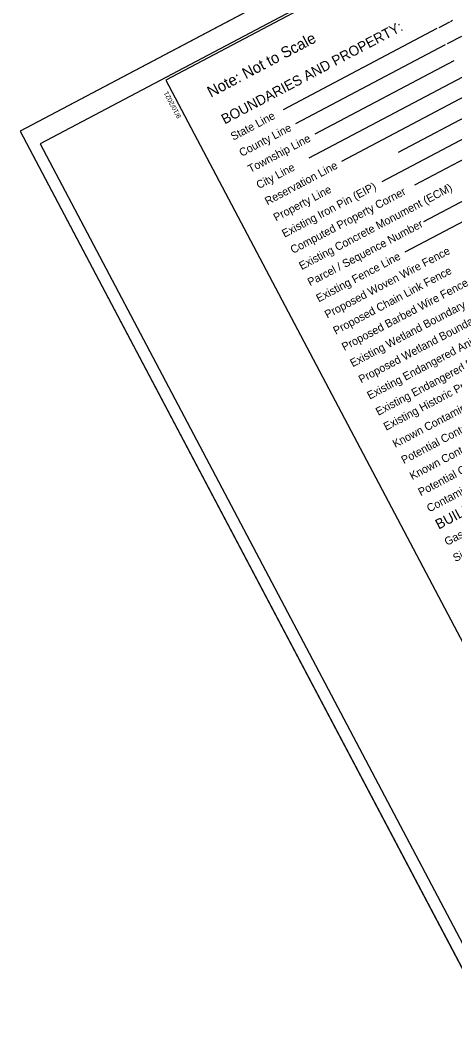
# Model space of a CAD drawing. Extents: x 1487118 to 1489121, y 496367 to 498126.
# Drawn here: x 1487118 to 1487593, y 496367 to 497462 of the extents above; entities that cross this region are included whole.
import ezdxf

# ---------------------------------------------------------------- set-up
doc = ezdxf.new("R2010")
doc.units = 0
for name, color, linetype in [('Sheet Cutting Line CELL', 7, 'Continuous'), ('Sheet Plot Border Inside CELL', 7, 'Continuous'), ('Sheet Plot Border Outside CELL', 7, 'Continuous'), ('Sheet Summary Guardrail CELL', 7, 'Continuous'), ('Sheet Symbology CELL', 7, 'Continuous')]:
    doc.layers.add(name, color=color, linetype=linetype)

msp = doc.modelspace()

# ---------------------------------------------------------------- linework, layer by layer
at = {"layer": 'Sheet Cutting Line CELL'}
for p, q in [((1488607.2, 498126.3), (1487118, 497340)), ((1487118, 497340), (1487631.6, 496367.3))]:
    msp.add_line(p, q, dxfattribs=at)
at = {"layer": 'Sheet Plot Border Inside CELL'}
msp.add_lwpolyline([(1487632.6, 496393.2), (1489106.3, 497171.4), (1488613.7, 498104.4), (1487140, 497326.3)], close=True, dxfattribs=at)
at = {"layer": 'Sheet Plot Border Outside CELL'}
msp.add_lwpolyline([(1487631.6, 496367.3), (1489120.8, 497153.6), (1488607.2, 498126.3), (1487118, 497340)], close=True, dxfattribs=at)
at = {"layer": 'Sheet Symbology CELL'}
for p, q in [((1487576, 497453.5), (1487587.7, 497459.7)), ((1487588.6, 497460.1), (1487590.8, 497461.3)), ((1487573.5, 497452.2), (1487405.5, 497363.5)), ((1487585.3, 497435.8), (1487600.9, 497444)), ((1487582.8, 497434.5), (1487419.2, 497348.1)), ((1487592.1, 497416.8), (1487440.3, 497336.6)), ((1487601.5, 497399.1), (1487433.5, 497310.4)), ((1487610.8, 497381.4), (1487469.3, 497306.7)), ((1487620.2, 497363.7), (1487531.2, 497316.8)), ((1487629.5, 497346.1), (1487513.4, 497284.8)), ((1487638.8, 497328.4), (1487549.1, 497281)), ((1487657.5, 497293), (1487559.1, 497241)), ((1487666.8, 497275.3), (1487538.5, 497207.6))]:
    msp.add_line(p, q, dxfattribs=at)
msp.add_lwpolyline([(1488603.8, 498096.3), (1487277.4, 497395.9), (1487767.2, 496468.3), (1489093.6, 497168.7)], close=True, dxfattribs=at)

# ---------------------------------------------------------------- texts
at = {"layer": 'Sheet Summary Guardrail CELL'}
msp.add_text('9/10/2021', height=5.25, rotation=117.8351, dxfattribs=at).set_placement((1487294.5, 497355.6))
at = {"layer": 'Sheet Symbology CELL'}
for s, height, p in [('BOUNDARIES AND PROPERTY:', 11, (1487341.7, 497347.3)), ('Note: Not to Scale', 12.108, (1487326.6, 497376.6)), ('State Line', 8.75, (1487351.1, 497329.6)), ('County Line', 8.75, (1487360.4, 497311.9)), ('Township Line', 8.75, (1487369.8, 497294.2)), ('City Line', 8.75, (1487379.1, 497276.6)), ('Reservation Line', 8.75, (1487388.4, 497258.9)), ('Property Line', 8.75, (1487397.8, 497241.2)), ('Existing Iron Pin (EIP)', 8.75, (1487407.1, 497223.5)), ('Computed Property Corner', 8.75, (1487416.4, 497205.8)), ('Existing Concrete Monument (ECM)', 8.75, (1487425.8, 497188.1)), ('Parcel / Sequence Number', 8.75, (1487435.1, 497170.4)), ('Proposed Woven Wire Fence', 8.75, (1487453.8, 497135.1)), ('Existing Fence Line', 8.75, (1487444.5, 497152.8)), ('Proposed Chain Link Fence', 8.75, (1487463.1, 497117.4)), ('Proposed Barbed Wire Fence', 8.75, (1487472.5, 497099.7)), ('Existing Wetland Boundary', 8.75, (1487481.6, 497081.9)), ('Existing Endangered Animal Boundary', 8.75, (1487500.2, 497046.5)), ('Proposed Wetland Boundary', 8.75, (1487490.9, 497064.2)), ('Existing Endangered Plant Boundary', 8.75, (1487509.6, 497028.8)), ('Existing Historic Property Boundary', 8.75, (1487518.2, 497012.5)), ('Known Contamination Area: Soil', 8.75, (1487528.1, 496993.7)), ('Potential Contamination Area: Soil', 8.75, (1487537.5, 496976)), ('Known Contamination Area: Water', 8.75, (1487546.7, 496958.5)), ('Potential Contamination Area: Water', 8.75, (1487556, 496940.9)), ('Contaminated Site: Known or Potential', 8.75, (1487565.4, 496923.2)), ('BUILDINGS AND OTHER CULTURE:', 11, (1487575.6, 496904.4)), ('Gas Pump Vent or U/G Tank Cap', 8.75, (1487584.7, 496886.6)), ('Sign', 8.75, (1487594, 496868.9))]:
    msp.add_text(s, height=height, rotation=27.8351, dxfattribs=at).set_placement(p)

doc.saveas('drawing.dxf')
